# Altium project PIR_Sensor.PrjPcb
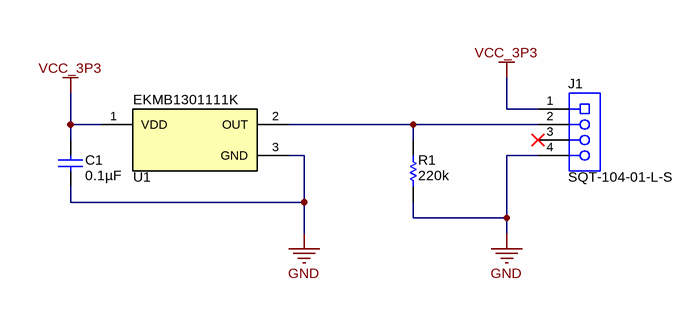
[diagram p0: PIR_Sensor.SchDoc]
TID: N/A; TechSupport: http://www.ti.com/support; SCH_Rev: A0; PRJ_Title: Change in menu Project|Project Options|Parameters; PRJ_Number: PIRSensor; PRJ_Engineer: Amit Ashara; PRJ_Customer: Public Release; PCB_Rev: A0; PCB_Layout: Amit Ashara; CopyrightYear: 2016
1 sheet, 4 parts. Net scope: global (net labels, ports and power ports of the same name join across sheets).
Board file: PIR_Sensor.PcbDoc

## Sheet PIR_Sensor.SchDoc
size 431 x 279 mm; Date: Not shown in title block; ApprovedBy: Not shown in title block; CheckedBy: Not shown in title block; Author: Not shown in title block; CompanyName: Not shown in title block; Engineer: Not shown in title block; Organization: Not shown in title block; Address1: Not shown in title block; Address2: Not shown in title block; Address3: Not shown in title block; Address4: Not shown in title block; DocumentNumber: 1; Revision: Use project parameter SCH_Rev; SheetNumber: 3; SheetTotal: 3; PageSetup: Record=PageOptions¦CenterHorizontal=True¦CenterVertical=True¦PrintScale=1.00¦XCorrection=1.00¦YCorrection=1.00¦PrintKind=0¦BorderSize=5000000¦LeftOffset=0¦BottomOffset=0¦Orientation=2¦PaperLength=1000¦PaperWidth=1000¦Scale=100¦PaperSource=15¦PrintQuality=600¦MediaType=1¦DitherType=10¦PaperKind=Letter¦PrintScaleMode=1

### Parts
C1  ValueDisplayed: 0.1µF  [0603]  (hidden comment: GRM188R70J104KA01D)
J1  SQT-104-01-L-S  [Samtec-SQT-104-01-L-S]
R1  ValueDisplayed: 220k  [0603]  (hidden comment: CRCW0603220KJNEA)
U1  EKMB1301111K  [Panasonic_EKMB1301111K]

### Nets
GND: C1.2 J1.4 R1.1 U1.3(GND)
VCC_3P3: C1.1 J1.1 U1.1(VDD)
NetJ1_2: J1.2 R1.2 U1.2(OUT)

Not connected (* = marked no-connect by the designer): J1 3*

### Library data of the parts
C1 = GRM188R70J104KA01D: CAP, CERM, 0.1 µF, 6.3 V, +/- 10%, X7R, 0603; Manufacturer: MuRata; Polarized: N; CompType: Capacitor; Value: 0.1uF; U/M: EA; Cap_F: 0.0000001; Tolerance_%: 10; Value1: Unknown; VDC_V: 6.3; Value2: 6.3V; TaMin_C: -55; TaMax_C: 125; SizeArea_mm2: 1.28; SizeAreaWB_mm2: 4.68; SizeX_mm: 1.6; SizeY_mm: 0.8; SizeZ_mm: 1; AEC Category: Q200
J1 = SQT-104-01-L-S: Receptacle, 2mm, 4x1, Gold, TH; Manufacturer: Samtec; SymbolCreator: a0411947
R1 = CRCW0603220KJNEA: RES, 220 k, 5%, 0.1 W, 0603; Manufacturer: Vishay-Dale; CompType: Resistor; Value: 220k; Res_ohm: 220000; Tolerance_%: 5; Power_W: 0.1; Value2: 0.1W; VDC_V: 75; TempCo: 200 ppm/C; SizeArea_mm2: 1.28; SizeX_mm: 1.6; SizeY_mm: 0.8; SizeZ_mm: 1; EIA_Code: E24; U/M: EA; AEC Category: Q200
U1 = EKMB1301111K: High-sensitive human detection sensor with built-in amp, TH; Manufacturer: Panasonic; SymbolCreator: Altium; SizeAreaWB_mm2: 169; SizeArea_mm2: 121; SizeX_mm: 11; SizeZ_mm: 14.9

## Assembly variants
001: not fitted FID1 FID2 FID3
